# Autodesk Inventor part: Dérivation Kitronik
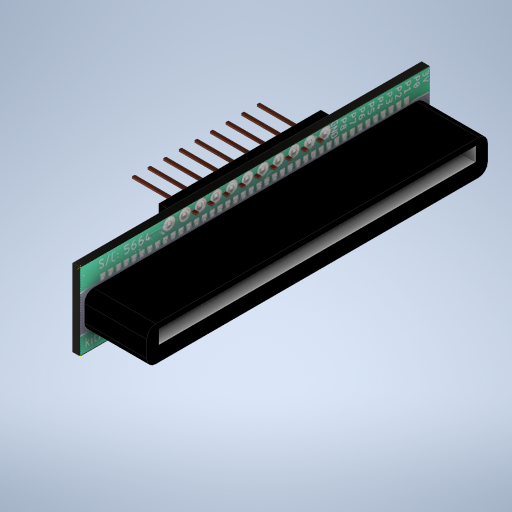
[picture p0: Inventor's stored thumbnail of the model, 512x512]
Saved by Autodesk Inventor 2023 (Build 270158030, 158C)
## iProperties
Created: 2022-12
Part Number: Dérivation Kitronik
Material: Générique
Document SubType Name: Modeling
Designer: ecuenot
Density: 1 g/cm^3
Appearance: Par défaut
Author: ecuenot
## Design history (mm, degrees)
sketch "Esquisse1"
  geometry: L1 (0, 0)-(12.8, 0); L2 (12.8, 0)-(12.8, -58.2); L3 (12.8, -58.2)-(0, -58.2); L4 (0, -58.2)-(0, 0); 1 further point
  constraints: 8 end point, 2 parallel, 2 point on line, 1 horizontal, 1 perpendicular
  dimensions: "d0" = 12.8 distance of L2.end L3.end; "d1" = 58.2 distance of L1.end L2.end
extrude "Extrusion1" new body sketch "Esquisse1" distance "d2" = 1.3; taper "d3" = 0 deg
sketch "Esquisse3"
  geometry: L1 (0, 12.8)-(58.215, 12.733); L2 (58.215, 12.733)-(58.2, 0); L3 (58.2, 0)-(-0.015, 0.067); L4 (-0.015, 0.067)-(0, 12.8); 3 further points; 1 other entity
  constraints: 2 coincident, 2 other
  node "Image2"
sketch "Esquisse4"
  geometry: L1 (58.2, 12.8)-(0, 12.8) reference; L2 (0, 12.8)-(-5.748, 12.8); L3 (57.5, 3)-(0.7, 3); L4 (0.7, 3)-(0.7, 8.8); L5 (0.7, 8.8)-(57.5, 8.8); L6 (57.5, 8.8)-(57.5, 3); 2 further points
  constraints: 10 end point, 2 horizontal, 2 parallel, 1 perpendicular
extrude "Extrusion2" join sketch "Esquisse4" distance "d36" = 10.4; taper "d37" = 0 deg
sketch "Esquisse5"
  geometry: L1 (2.7, 7.8)-(55.5, 7.8); L2 (2.7, 5.5)-(55.5, 5.5); L3 (57.5, 18.918)-(55.5, 18.918); L4 (55.5, 7.8)-(55.5, 5.5); L5 (2.7, 7.8)-(2.7, 5.5); 1 further point
  constraints: 10 end point, 1 perpendicular, 1 vertical
  dimensions: "d41" = 2 distance of L3.start L3.end
extrude "Extrusion3" cut sketch "Esquisse5" distance "d42" = 8; taper "d43" = 0 deg
fillet "Congé1" dims "d44" = 1.5
sketch "Esquisse6"
  geometry: L1 (0, 0)-(-58.2, 0) reference; L2 (0, 12.8)-(0, 0) reference; L3 (-18.6, 1.15)-(-19.1, 1.15); L4 (-19.1, 1.15)-(-19.1, 1.4); L5 (-19.1, 1.4)-(-18.6, 1.4); L6 (-18.6, 1.4)-(-18.6, 1.15)
  constraints: 8 end point, 2 parallel, 1 horizontal, 1 perpendicular
extrude "Extrusion4" join sketch "Esquisse6" distance "d49" = 8.7; taper "d50" = 0 deg; dims "d53" = 2, "d54" = 0
fillet "Congé2" dims "d51" = 0.1
fillet "Congé3" dims "d52" = 0.1
sketch "Esquisse7"
  geometry: L1 (-58.2, 0)-(-58.2, 12.8) reference; L2 (-58.2, 12.8)-(-58.2, 14.55); L3 (-42.9, 12.7)-(-15.9, 12.7); L4 (-15.9, 12.7)-(-15.9, 10.8); L5 (-15.9, 10.8)-(-42.9, 10.8); L6 (-42.9, 10.8)-(-42.9, 12.7); L7 (-42.9, 10.8)-(-42.9, 12.7); L8 (-42.9, 12.7)-(-15.9, 12.7); L9 (-35.293, 0)-(-34.511, 0); L10 (-42.9, 0.1)-(-15.9, 0.1); L11 (-42.9, 0.1)-(-42.9, 2); L12 (-42.9, 2)-(-15.9, 2); L13 (-15.9, 2)-(-15.9, 0.1)
  constraints: 24 end point, 4 perpendicular, 2 parallel, 2 vertical, 1 horizontal, 1 point on line
  dimensions: "d75" = 1.9 distance of L5.end L7.end; "d79" = 1.9 distance of L10.start L11.end
extrude "Extrusion5" join sketch "Esquisse7" distance "d72" = 1.5; taper "d73" = 0 deg
sketch "Esquisse8"
  geometry: L1 (-58.2, 12.8)-(0.015, 12.733); L2 (0.015, 12.733)-(0, 0); L3 (0, 0)-(-58.215, 0.067); L4 (-58.215, 0.067)-(-58.2, 12.8); 2 further points; 1 other entity
  constraints: 2 coincident, 2 other
feature "Décalcomanie1" sketch "Esquisse8"
node "Solide1"
pattern_linear "Réseau rectangulaire2" dims "d63" = 2.6, "d66" = 10.25
node "Image3"
